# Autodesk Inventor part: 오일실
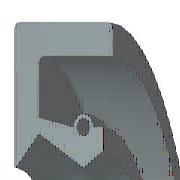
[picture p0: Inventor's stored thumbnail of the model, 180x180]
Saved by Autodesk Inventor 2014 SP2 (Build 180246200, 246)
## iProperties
IsCustomPart: 0
Created: 2009-02
Part Number: 오일실
Material: 고무
Description: 오일-실
Document SubType Name: Modeling
Standard: KS B 2804
Designer: KYOUNG IL JANG
Standards Organization: KS
Language: ko-KR
Size Designation: D - 20 32 8
Categories: <MemberInstance><Categories><Category DisplayName="샤프트 부품" InternalName="7f7aeb1f-a693-4053-b835-cee3144e0d98" Mnemonic="SHFT"><Category DisplayName="실링" Intern
Density: 0.93 g/cm^3
Mass: 2.19344 g
Surface Area: 31.4782 cm^2
Volume: 2.35853 cm^3
Appearance: 고무 - 검은색 - 버전 1.1
Author: KYOUNG IL JANG
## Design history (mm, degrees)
revolve "본체" stored, may be unused: angle "d17" = 90 deg
revolve "스프링1" stored, may be unused: angle "d18" = 90 deg
body "Solid1"
sketch "스케치1"
  geometry: L1 (0, 16)-(8, 16); L2 (8, 14.25)-(1.75, 14.25); L3 (1.75, 11.75)-(4.9, 10); L4 (4.9, 10)-(0, 10); L5 (0, 0)-(9.586, 0) reference; L6 (4.9, 10)-(6.3, 10.875); L7 (0, 18)-(0, -3) reference; L8 (-1.941, 0)-(11.507, 0) reference; L9 (4.2, 12.1)-(1.75, 12.71); L10 (1.75, 12.71)-(1.75, 14.25); L11 (0, 16)-(0, 10.088); L12 (4.9, 10)-(0, 10); L13 (1.75, 11.75)-(0.152, 10.028); L14 (8, 16)-(8, 14.25); L15 (5.6, 12.1)-(6.3, 12.1); L16 (6.3, 12.1)-(6.3, 10.875); C1 r 0.455 at (4.9, 12.1); A1 r 0.7 centre (4.9, 12.1) between (5.6, 12.1) and (4.2, 12.1); A2 r 0.088 centre (0.088, 10.088) between (0, 10.088) and (0.152, 10.028); 1 further point
  constraints: 28 end point, 5 horizontal alignment, 5 point on line, 4 point on circle, 4 vertical alignment, 3 centre point, 3 tangent, 2 collinear, 2 horizontal, 2 perpendicular, 1 coincident, 1 parallel
  dimensions: "d0" = 32 diameter of L1 L5 (= SD2); "d1" = 1.75 distance of L1.end L2.start (= SD); "d2" = 0.91 diameter of C1 (= SPDI); "d3" = 1.4 diameter of A1 (= SPDA); "d4" = 20 diameter of L3.end L5 (= NND); "d5" = 23.5 diameter of L3.start L5 (= TKDM); "d7" = 25.42 diameter of L9.end L5 (= TKDM + 0.24 x SWDT); "d8" = 1.75 distance between parallel lines of L11 L10 (= SD); "d9" = 4.9 distance from line of L11 C1.centre (= SPDST); "d10" = 24.2 diameter of C1.centre L5 (= HLDM); "d11" = 0.0875 radius of A2 (= 0.25 x LAB); "d12" = 6.3 distance between parallel lines of L11 L16 (= SDI); "d13" = 21.75 diameter of L6.end L5 (= ABDM); "d14" = 8 distance from line of L11 L1.end (= SWDT)
fillet "모깎기1" dims "d6" = 0.3 (= RR)
other parameters: "SD2" = 32 [user parameter; used in 1 equation term], "SWDT" = 8 [user parameter; used in 2 equation terms], "RR" = 0.3 [user parameter; used in 1 equation term], "SD" = 1.75 [user parameter; used in 2 equation terms], "NND" = 20 [user parameter; used in 1 equation term], "SPDA" = 1.4 [user parameter; used in 1 equation term], "SPDI" = 0.91 [user parameter; used in 1 equation term], "TKDM" = 23.5 [user parameter; used in 2 equation terms], "HLDM" = 24.2 [user parameter; used in 1 equation term], "ABDM" = 21.75 [user parameter; used in 1 equation term], "SDI" = 6.3 [user parameter; used in 1 equation term], "SPDST" = 4.9 [user parameter; used in 1 equation term], "LAB" = 0.35 [user parameter; used in 1 equation term], "d15" = 0, "d16" = 0, "d19" = 0
